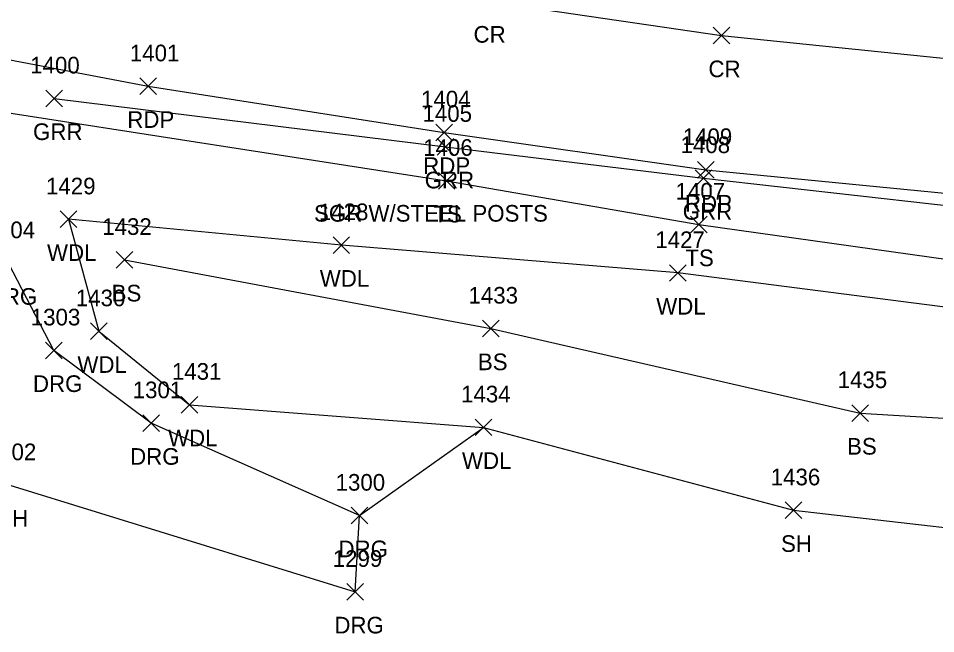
# Model space of a CAD drawing. Extents: x 1547013 to 1549434, y 267998 to 268739.
# Drawn here: x 1548667.4 to 1548777.6, y 268005 to 268079 of the extents above; entities that cross this region are included whole.
import ezdxf

# ---------------------------------------------------------------- set-up
doc = ezdxf.new("R2010")
doc.units = 0
for name, color, linetype in [('L_A', 7, 'Continuous'), ('L_I', 7, 'Continuous'), ('L_TIC', 7, 'Continuous'), ('LAWA', 7, 'Continuous'), ('LELB', 7, 'Continuous'), ('LSOGP', 7, 'Continuous'), ('P_A', 7, 'Continuous'), ('P_I', 7, 'Continuous'), ('P_TIC', 7, 'Continuous'), ('PET', 7, 'Continuous'), ('PRC', 7, 'Continuous'), ('R_A', 7, 'Continuous'), ('R_C', 7, 'Continuous'), ('R_I', 7, 'Continuous'), ('R_TIC', 7, 'Continuous'), ('RDG', 7, 'Continuous'), ('RGR', 7, 'Continuous')]:
    doc.layers.add(name, color=color, linetype=linetype)

msp = doc.modelspace()

# ---------------------------------------------------------------- linework, layer by layer
at = {"layer": 'L_TIC'}
for points in [[(1548717.89, 268058.45), (1548719.89, 268060.45)], [(1548719.89, 268058.45), (1548717.89, 268060.45)], [(1548672.48, 268053.82), (1548674.48, 268055.82)], [(1548674.48, 268053.82), (1548672.48, 268055.82)], [(1548748.16, 268053.19), (1548750.16, 268055.19)], [(1548750.16, 268053.19), (1548748.16, 268055.19)], [(1548705.24, 268050.72), (1548707.24, 268052.72)], [(1548707.24, 268050.72), (1548705.24, 268052.72)], [(1548679.21, 268048.95), (1548681.21, 268050.95)], [(1548681.21, 268048.95), (1548679.21, 268050.95)], [(1548745.65, 268047.37), (1548747.65, 268049.37)], [(1548747.65, 268047.37), (1548745.65, 268049.37)], [(1548723.2, 268040.69), (1548725.2, 268042.69)], [(1548725.2, 268040.69), (1548723.2, 268042.69)], [(1548676.13, 268040.37), (1548678.13, 268042.37)], [(1548678.13, 268040.37), (1548676.13, 268042.37)], [(1548687.02, 268031.54), (1548689.02, 268033.54)], [(1548689.02, 268031.54), (1548687.02, 268033.54)], [(1548767.54, 268030.54), (1548769.54, 268032.54)], [(1548769.54, 268030.54), (1548767.54, 268032.54)], [(1548722.32, 268028.82), (1548724.32, 268030.82)], [(1548724.32, 268028.82), (1548722.32, 268030.82)], [(1548759.56, 268018.85), (1548761.56, 268020.85)], [(1548761.56, 268018.85), (1548759.56, 268020.85)]]:
    msp.add_lwpolyline(points, dxfattribs=at)
at = {"layer": 'LAWA'}
msp.add_lwpolyline([(1548862.84, 268037.49), (1548819.36, 268041.09), (1548782.15, 268043.82), (1548746.65, 268048.37), (1548706.24, 268051.72), (1548673.48, 268054.82), (1548677.13, 268041.37), (1548688.02, 268032.54), (1548723.32, 268029.82)], dxfattribs=at)
at = {"layer": 'LELB'}
for points in [[(1548662.66, 268068.17), (1548718.89, 268059.45), (1548749.16, 268054.19), (1548786.26, 268048.98), (1548815.59, 268046.57), (1548864.84, 268043.79)], [(1548680.21, 268049.95), (1548724.2, 268041.69), (1548768.54, 268031.54), (1548796.61, 268029.85), (1548828.81, 268024.84), (1548861.13, 268023.69)]]:
    msp.add_lwpolyline(points, dxfattribs=at)
at = {"layer": 'LSOGP'}
msp.add_lwpolyline([(1548666.42, 268022.87), (1548707.91, 268010.05), (1548708.41, 268019.21), (1548723.32, 268029.82), (1548760.56, 268019.85), (1548794.77, 268015.95)], dxfattribs=at)
at = {"layer": 'P_TIC'}
for points in [[(1548750.9, 268075.9), (1548752.9, 268077.9)], [(1548752.9, 268075.9), (1548750.9, 268077.9)], [(1548682.04, 268069.81), (1548684.04, 268071.81)], [(1548684.04, 268069.81), (1548682.04, 268071.81)], [(1548717.59, 268064.27), (1548719.59, 268066.27)], [(1548719.59, 268064.27), (1548717.59, 268066.27)], [(1548749.02, 268059.75), (1548751.02, 268061.75)], [(1548751.02, 268059.75), (1548749.02, 268061.75)]]:
    msp.add_lwpolyline(points, dxfattribs=at)
at = {"layer": 'PET'}
msp.add_lwpolyline([(1548277.31, 268222.58), (1548324.08, 268200.05), (1548370.89, 268177.56), (1548421.34, 268155.12), (1548457.66, 268139.55), (1548491.25, 268126.1), (1548528.96, 268112.02), (1548568.2, 268099.41), (1548604.28, 268089.49), (1548621.9, 268083.87), (1548638.12, 268079.83), (1548660.94, 268075.04), (1548683.04, 268070.81), (1548718.59, 268065.27), (1548750.02, 268060.75), (1548786.09, 268057.26), (1548818, 268054.36), (1548866.14, 268051.84)], dxfattribs=at)
at = {"layer": 'PRC'}
msp.add_lwpolyline([(1548285.23, 268237.15), (1548330.43, 268214.75), (1548376.37, 268192.58), (1548426.54, 268169.59), (1548464.29, 268153.5), (1548497.35, 268140.09), (1548534.69, 268126.49), (1548572.93, 268114.69), (1548608.02, 268104.77), (1548637.81, 268097.38), (1548663.07, 268091.69), (1548686.38, 268086.96), (1548723.69, 268081.05), (1548751.9, 268076.9), (1548786.74, 268073.36), (1548818.76, 268070.54), (1548866.8, 268068.08)], dxfattribs=at)
at = {"layer": 'R_TIC'}
for points in [[(1548670.73, 268068.35), (1548672.73, 268070.35)], [(1548672.73, 268068.35), (1548670.73, 268070.35)], [(1548717.76, 268062.54), (1548719.76, 268064.54)], [(1548719.76, 268062.54), (1548717.76, 268064.54)], [(1548748.75, 268058.78), (1548750.75, 268060.78)], [(1548750.75, 268058.78), (1548748.75, 268060.78)], [(1548670.71, 268038.07), (1548672.71, 268040.07)], [(1548672.71, 268038.07), (1548670.71, 268040.07)], [(1548682.39, 268029.32), (1548684.39, 268031.32)], [(1548684.39, 268029.32), (1548682.39, 268031.32)], [(1548707.41, 268018.21), (1548709.41, 268020.21)], [(1548709.41, 268018.21), (1548707.41, 268020.21)], [(1548706.91, 268009.05), (1548708.91, 268011.05)], [(1548708.91, 268009.05), (1548706.91, 268011.05)]]:
    msp.add_lwpolyline(points, dxfattribs=at)
at = {"layer": 'RDG'}
msp.add_lwpolyline([(1548707.91, 268010.05), (1548708.41, 268019.21), (1548683.39, 268030.32), (1548671.71, 268039.07), (1548666.28, 268049.55), (1548656.69, 268072.33)], dxfattribs=at)
at = {"layer": 'RGR'}
msp.add_lwpolyline([(1548671.73, 268069.35), (1548718.76, 268063.54), (1548749.75, 268059.78), (1548786.73, 268055.59), (1548817.74, 268053.07), (1548866.07, 268050.79)], dxfattribs=at)

# ---------------------------------------------------------------- texts
at = {"layer": 'L_A'}
for s, p in [('TS', (1548717.3, 268054.45)), ('WDL', (1548670.89, 268049.82)), ('TS', (1548747.56, 268049.19)), ('WDL', (1548703.65, 268046.72)), ('BS', (1548678.65, 268044.95)), ('WDL', (1548744.06, 268043.37)), ('WDL', (1548674.54, 268036.37)), ('BS', (1548722.64, 268036.69)), ('WDL', (1548685.43, 268027.54)), ('BS', (1548766.98, 268026.54)), ('WDL', (1548720.73, 268024.82)), ('SH', (1548664.91, 268017.87)), ('SH', (1548759.05, 268014.85))]:
    msp.add_text(s, height=2, dxfattribs=at).set_placement(p)
at = {"layer": 'L_I'}
for s, p in [('1406', (1548716.07, 268062.45)), ('1429', (1548670.77, 268057.82)), ('1407', (1548746.38, 268057.19)), ('1428', (1548703.54, 268054.72)), ('1432', (1548677.52, 268052.95)), ('1427', (1548743.95, 268051.37)), ('1430', (1548674.35, 268044.37)), ('1433', (1548721.51, 268044.69)), ('1431', (1548685.89, 268035.54)), ('1435', (1548765.85, 268034.54)), ('1434', (1548720.62, 268032.82)), ('1302', (1548663.65, 268025.87)), ('1436', (1548757.81, 268022.85))]:
    msp.add_text(s, height=2, dxfattribs=at).set_placement(p)
at = {"layer": 'P_A'}
for s, p in [('CR', (1548722.12, 268076.05)), ('CR', (1548750.33, 268071.9)), ('RDP', (1548680.53, 268065.81)), ('RDP', (1548716.07, 268060.27)), ('RDP', (1548747.51, 268055.75))]:
    msp.add_text(s, height=2, dxfattribs=at).set_placement(p)
at = {"layer": 'P_I'}
for s, p in [('1401', (1548680.84, 268073.81)), ('1404', (1548715.81, 268068.27)), ('1409', (1548747.24, 268063.75))]:
    msp.add_text(s, height=2, dxfattribs=at).set_placement(p)
at = {"layer": 'R_A'}
for s, p in [('GRR', (1548669.21, 268064.35)), ('GRR', (1548716.25, 268058.54)), ('GRR', (1548747.24, 268054.78)), ('DRG', (1548663.77, 268044.55)), ('DRG', (1548669.2, 268034.07)), ('DRG', (1548680.87, 268025.32)), ('DRG', (1548705.9, 268014.21)), ('DRG', (1548705.4, 268005.05))]:
    msp.add_text(s, height=2, dxfattribs=at).set_placement(p)
at = {"layer": 'R_C'}
msp.add_text('SGR W/STEEL POSTS', height=2, dxfattribs=at).set_placement((1548702.96, 268054.54))
at = {"layer": 'R_I'}
for s, p in [('1400', (1548668.87, 268072.35)), ('1405', (1548715.99, 268066.54)), ('1408', (1548746.98, 268062.78)), ('1304', (1548663.51, 268052.55)), ('1303', (1548668.94, 268042.07)), ('1301', (1548681.18, 268033.32)), ('1300', (1548705.55, 268022.21)), ('1299', (1548705.21, 268013.05))]:
    msp.add_text(s, height=2, dxfattribs=at).set_placement(p)

doc.saveas('drawing.dxf')
